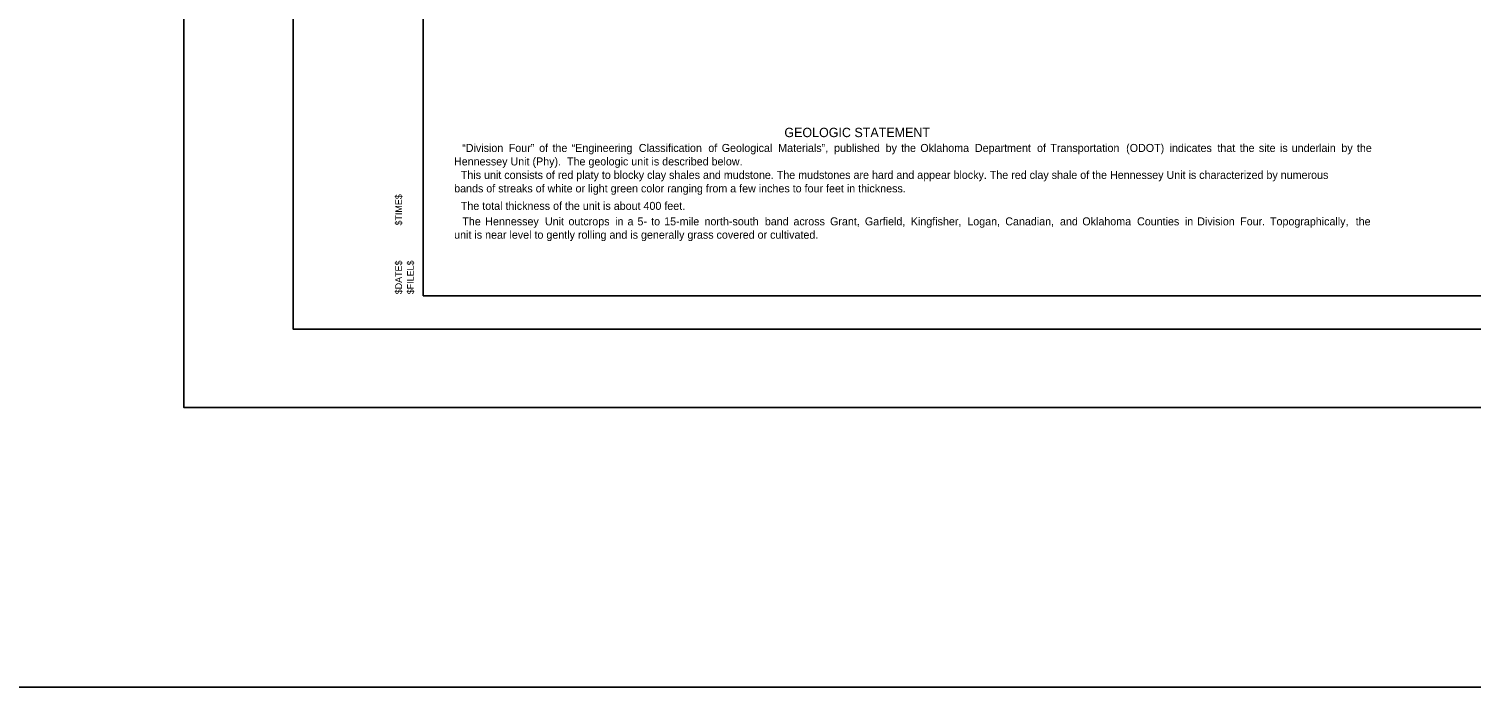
# Model space of a CAD drawing. Extents: x -6 to 173, y 24 to 64.
# Drawn here: x 129.33 to 150.95, y 25.78 to 35.65 of the extents above; entities that cross this region are included whole.
import ezdxf

# ---------------------------------------------------------------- set-up
doc = ezdxf.new("R2010")
doc.units = 0
for name, color, linetype in [('S', 7, 'Continuous'), ('SHT_Plot_Shape_Full', 7, 'Continuous'), ('SHT_Plot_Shape_Half', 7, 'Continuous'), ('SHT_Plot_Stamp', 7, 'Continuous'), ('SHT_Sheet_Border', 7, 'Continuous'), ('Text', 7, 'Continuous')]:
    doc.layers.add(name, color=color, linetype=linetype)

# ---------------------------------------------------------------- blocks, each defined once
blk = doc.blocks.new('Stamp_Plot_Stamp')
at = {"layer": 'SHT_Plot_Stamp'}
for s, p in [('$TIME$', (1.695, 1.572)), ('$DATE$', (1.695, 0.542)), ('$FILEL$', (1.873, 0.542))]:
    blk.add_text(s, height=0.1, rotation=90, dxfattribs=at).set_placement(p)

msp = doc.modelspace()

# ---------------------------------------------------------------- linework, layer by layer
at = {"layer": 'S'}
msp.add_lwpolyline([(-6.024, 64.421), (172.576, 64.421), (172.576, 25.783), (-6.024, 25.783)], close=True, dxfattribs=at)
at = {"layer": 'SHT_Plot_Shape_Full'}
msp.add_lwpolyline([(131.656, 53.971), (167.656, 53.971), (167.656, 29.971), (131.656, 29.971)], close=True, dxfattribs=at)
at = {"layer": 'SHT_Plot_Shape_Half'}
msp.add_lwpolyline([(133.294, 53.146), (167.294, 53.146), (167.294, 31.146), (133.294, 31.146)], close=True, dxfattribs=at)
at = {"layer": 'SHT_Sheet_Border'}
msp.add_lwpolyline([(135.244, 52.646), (166.744, 52.646), (166.744, 31.646), (135.244, 31.646)], close=True, dxfattribs=at)

# ---------------------------------------------------------------- block references
at = {"layer": 'SHT_Plot_Stamp'}
msp.add_blockref('Stamp_Plot_Stamp', (133.23, 31.127), dxfattribs=at)

# ---------------------------------------------------------------- texts
at = {"layer": 'Text'}
for s, height, p in [('GEOLOGIC STATEMENT', 0.14, (140.658, 34.023)), ('“Division', 0.12, (135.829, 33.801)), ('Four”', 0.12, (136.526, 33.801)), ('of', 0.12, (136.982, 33.801)), ('the', 0.12, (137.182, 33.801)), ('“Engineering', 0.12, (137.47, 33.801)), ('Classification', 0.12, (138.476, 33.801)), ('of', 0.12, (139.518, 33.801)), ('Geological', 0.12, (139.719, 33.801)), ('Materials”,', 0.12, (140.566, 33.801)), ('published', 0.12, (141.403, 33.801)), ('by', 0.12, (142.176, 33.801)), ('the', 0.12, (142.408, 33.801)), ('Oklahoma', 0.12, (142.696, 33.801)), ('Department', 0.12, (143.515, 33.801)), ('of', 0.12, (144.446, 33.801)), ('Transportation', 0.12, (144.646, 33.801)), ('(ODOT)', 0.12, (145.782, 33.801)), ('indicates', 0.12, (146.433, 33.801)), ('that', 0.12, (147.15, 33.801)), ('the', 0.12, (147.484, 33.801)), ('site', 0.12, (147.772, 33.801)), ('is', 0.12, (148.088, 33.801)), ('underlain', 0.12, (148.264, 33.801)), ('by', 0.12, (149.009, 33.801)), ('the ', 0.12, (149.241, 33.801)), ('Hennessey Unit (Phy).  The geologic unit is described below.', 0.12, (135.705, 33.599)), ('  This unit consists of red platy to blocky clay shales and mudstone. The mudstones are hard and appear blocky. The red clay shale of the Hennessey Unit is characterized by numerous ', 0.12, (135.719, 33.397)), ('bands of streaks of white or light green color ranging from a few inches to four feet in thickness.', 0.12, (135.708, 33.195)), ('  The total thickness of the unit is about 400 feet.', 0.12, (135.719, 32.933)), ('The', 0.12, (135.83, 32.701)), ('Hennessey', 0.12, (136.174, 32.701)), ('Unit', 0.12, (137.069, 32.701)), ('outcrops', 0.12, (137.422, 32.701)), ('in', 0.12, (138.121, 32.701)), ('a', 0.12, (138.307, 32.701)), ('5-', 0.12, (138.456, 32.701)), ('to', 0.12, (138.661, 32.701)), ('15-mile', 0.12, (138.856, 32.701)), ('north-south', 0.12, (139.461, 32.701)), ('band', 0.12, (140.365, 32.701)), ('across', 0.12, (140.794, 32.701)), ('Grant,', 0.12, (141.343, 32.701)), ('Garfield,', 0.12, (141.865, 32.701)), ('Kingfisher,', 0.12, (142.554, 32.701)), ('Logan,', 0.12, (143.401, 32.701)), ('Canadian,', 0.12, (143.97, 32.701)), ('and', 0.12, (144.79, 32.701)), ('Oklahoma', 0.12, (145.125, 32.701)), ('Counties', 0.12, (145.945, 32.701)), ('in', 0.12, (146.662, 32.701)), ('Division', 0.12, (146.848, 32.701)), ('Four.', 0.12, (147.491, 32.701)), ('Topographically,', 0.12, (147.938, 32.701)), ('the ', 0.12, (149.223, 32.701)), ('unit is near level to gently rolling and is generally grass covered or cultivated.  ', 0.12, (135.708, 32.501))]:
    msp.add_text(s, height=height, dxfattribs=at).set_placement(p)

doc.saveas('drawing.dxf')
